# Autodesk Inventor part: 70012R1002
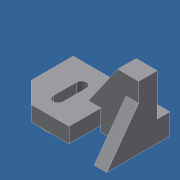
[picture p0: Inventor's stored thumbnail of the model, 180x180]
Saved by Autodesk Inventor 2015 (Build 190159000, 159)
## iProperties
Created: 2020-01
Part Number: 70012R1002
Material: 일반
Document SubType Name: Modeling
Designer: H09
Density: 1 g/cm^3
Appearance: 기본값
Author: H09
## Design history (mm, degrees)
sketch "스케치1"
  geometry: L1 (-35, 53)-(80, 53); L2 (80, 53)-(80, 16); L3 (35, -22)-(-10, -22); L4 (-35, 3)-(-35, 53); L5 (35, -22)-(35, 16); L6 (35, 16)-(80, 16); L7 (80, 16)-(65, 16); L8 (65, 16)-(65, -22); L9 (65, -22)-(80, -22); L10 (80, -22)-(80, 16); L11 (0, 28)-(0, 0); L12 (6, 28)-(6, 0); L13 (-6, 0)-(-6, 28); L14 (-35, 3)-(-10, -22); C1 r 16 at (0, 0); C2 r 10 at (0, 0); A1 r 6 centre (0, 28) between (6, 28) and (-6, 28); A2 r 6 centre (0, 0) between (-6, 0) and (6, 0); 2 further points
  constraints: 30 end point, 5 parallel, 4 centre point, 4 point on circle, 4 tangent, 3 coincident, 2 horizontal, 2 perpendicular, 2 vertical, 1 midpoint
  dimensions: "d0" = 16 radius of C1; "d1" = 10 radius of C2; "d2" = 38 distance between parallel lines of L6 L3; "d3" = 35 distance from line of L4 point (0, 0); "d4" = 53 distance from line of L1 point (0, 0); "d5" = 75 distance between parallel lines of L3 L1; "d6" = 45 distance of L5.end L2.end; "d7" = 115 distance of L1.start L1.end; "d8" = 38 distance between parallel lines of L9 L6; "d9" = 15 distance between parallel lines of L10 L8; "d10" = 28 distance of L11.start L11.end; "d11" = 6 radius of A1; "d12" = 25 horizontal distance of L4.start L3.end; "d13" = 45 deg angle of L14 L3
extrude "돌출1" new body sketch "스케치1" distance "d14" = 60; taper "d15" = 0 deg
sketch "스케치2"
  geometry: L1 (0, 0)-(-52.303, 38); L2 (0, 38)-(-60, 38) reference; L3 (-52.303, 38)-(-60, 38); L4 (-60, 38)-(-60, 0); L5 (-60, 0)-(0, 0); 1 further point
  constraints: 8 end point, 3 point on line, 1 collinear, 1 horizontal, 1 perpendicular
  dimensions: "d16" = 144 deg angle of L1 L2
extrude "돌출2" cut sketch "스케치2" stored distance "d17" = 40; taper "d18" = 0 deg
extrude "돌출3" join sketch "스케치1" distance "d19" = 25; taper "d20" = 0 deg
sketch "스케치3"
  geometry: L1 (-25, 7)-(45, 7); L2 (45, 7)-(45, 0); L3 (45, 0)-(-25, 0); L4 (-25, 0)-(-25, 7); 2 further points
  constraints: 8 end point, 2 parallel, 1 coincident, 1 horizontal, 1 perpendicular
  dimensions: "d21" = 7 distance between parallel lines of L3 L1; "d22" = 70 distance between parallel lines of L2 L4
extrude "돌출4" cut sketch "스케치3" stored distance "d23" = 25; taper "d24" = 0 deg
extrude "돌출5" join sketch "스케치1" distance "d25" = 7; taper "d26" = 0 deg
sketch "스케치4"
  geometry: L1 (-6, 0)-(-6, 28) reference; L2 (6, 28)-(6, 0) reference; A1 r 6 centre (0, 28) between (6, 28) and (-6, 28) reference; A2 r 6 centre (0, 0) between (-6, 0) and (6, 0) reference; 1 further point
extrude "돌출6" cut sketch "스케치4" distance "d27" = 12; taper "d28" = 0 deg
sketch "스케치5"
  geometry: L1 (45, 0)-(45, 50); L2 (45, 50)-(20, 50); L3 (20, 50)-(-15.01, 0); L4 (-15.01, 0)-(45, 0); 2 further points
  constraints: 8 end point, 2 horizontal, 1 coincident, 1 vertical
  dimensions: "d29" = 25 distance of L1.end L2.end; "d30" = 55 deg angle of L3 L2; "d31" = 50 distance between parallel lines of L4 L2
extrude "돌출7" join sketch "스케치5" distance "d32" = 22; taper "d33" = 0 deg
node "솔리드1"
